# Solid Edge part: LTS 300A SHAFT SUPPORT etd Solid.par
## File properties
Author: davee
Template: Normal.par
Last saved by: davee
Revision: 8
Application: Solid Edge
Accuracy: 0.990
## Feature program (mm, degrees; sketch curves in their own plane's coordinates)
sketch for "unnamed Protrusion 1" #1 plane through (0, 0, 0) normal (0, 0, 1) x-axis (1, 0, 0)
  line (9.5, -14.5) -> (28.5, -14.5)
  line (28.5, -14.5) -> (28.5, 10)
  line (28.5, 10) -> (9.5, 10)
  line (9.5, 10) -> (9.5, -14.5)
sketch for "unnamed Protrusion 1" #2 plane through (0, 0, 0) normal (0, 0, 1) x-axis (1, 0, 0)
  line (-28.5, -10) -> (-9.5, -10)
  line (-9.5, -10) -> (-9.5, 10)
  line (-9.5, 10) -> (-28.5, 10)
  line (-28.5, 10) -> (-28.5, -10)
  dimension (linear) = 9.5
  dimension (linear) = 28.5
  dimension (linear) = 28.5
  dimension (linear) = 28.5
extrude "unnamed Protrusion 1" add finite 13 along +normal
sketch for "ExtrudedProtrusion_2" plane through (-18.5, 0, 13) normal (0, 0, 1) x-axis (1, 0, 0)
  line (-10, 10) -> (47, 10)
  line (47, 2) -> (47, 10)
  line (-10, 2) -> (47, 2)
  line (-10, 10) -> (-10, 2)
extrude "ExtrudedProtrusion_2" add finite 57.5 along +normal
sketch for "unnamed Cutout 1" plane through (0, 2, 41.75) normal (0, -1, 0) x-axis (1, 0, 0)
  circle centre (0, 2.25) radius 10
extrude "unnamed Cutout 1" cut through along -normal
sketch for "ExtrudedCutout_2" plane through (0, 2, 41.75) normal (0, -1, 0) x-axis (1, 0, 0)
  line (2.45, 13.25) -> (6.3509, 13.25)
  line (6.3509, 13.25) -> (12.7017, 2.25)
  line (12.7017, 2.25) -> (6.3509, -8.75)
  line (2.45, -8.75) -> (6.3509, -8.75)
  line (2.45, -7.75) -> (2.45, -8.75)
  line (-2.45, -7.75) -> (2.45, -7.75)
  line (-2.45, -7.75) -> (-2.45, -8.75)
  line (-6.3509, -8.75) -> (-2.45, -8.75)
  line (-12.7017, 2.25) -> (-6.3509, -8.75)
  line (-6.3509, 13.25) -> (-12.7017, 2.25)
  line (-6.3509, 13.25) -> (-2.45, 13.25)
  line (-2.45, 13.25) -> (-2.45, 12.25)
  line (-2.45, 12.25) -> (2.45, 12.25)
  line (2.45, 12.25) -> (2.45, 13.25)
  dimension (linear) = 6.3509
  dimension (linear) = 6.3509
  dimension (linear) = 6.3509
  dimension (linear) = 12.7017
  dimension (linear) = 6.3509
  dimension (linear) = 12.7017
  dimension (linear) = 2.45
  dimension (linear) = 2.45
extrude "ExtrudedCutout_2" cut finite 4 along -normal
sketch for "Hole_1" plane through (-18.5, 0, 0) normal (0, 0, -1) x-axis (1, 0, 0)
  hole centre (35.5, 6.5) bore radius 1.1
hole "Hole_1" diameter 2.2 through
sketch for "unnamed Hole 1" plane through (-18.5, 0, 0) normal (0, 0, -1) x-axis (1, 0, 0)
  hole centre (1.5, 2) bore radius 1.1
hole "unnamed Hole 1" through
sketch for "Hole_3" plane through (-18.5, 0, 0) normal (0, 0, -1) x-axis (1, 0, 0)
  hole centre (1.5, 2) bore radius 2.2
hole "Hole_3" diameter 4.4 finite  VBottomAngle = 118 deg
sketch for "unnamed Hole 2" plane through (-18.5, 0, 0) normal (0, 0, -1) x-axis (1, 0, 0)
  hole centre (35.5, 6.5) bore radius 2.2
hole "unnamed Hole 2" finite
sketch for "Hole_5" plane through (-19, 0, 0) normal (0, 0, -1) x-axis (1, 0, 0)
  hole centre (-2, 2) bore radius 1.65
hole "Hole_5" diameter 3.3 through
sketch for "unnamed Hole 3" plane through (-19, 0, 0) normal (0, 0, -1) x-axis (1, 0, 0)
  hole centre (40, 6.5) bore radius 1.65
hole "unnamed Hole 3" through
sketch for "ExtrudedCutout_3" #1 plane through (-19, -4, 0) normal (0, 0, -1) x-axis (1, 0, 0)
  line (36, 1.5) -> (40, 1.5)
  line (40, 1.5) -> (40, 3.5)
  line (40, 3.5) -> (36, 3.5)
  line (36, 3.5) -> (36, 1.5)
sketch for "ExtrudedCutout_3" #2 plane through (-19, -4, 0) normal (0, 0, -1) x-axis (1, 0, 0)
  line (-2, -3) -> (2, -3)
  line (2, -3) -> (2, -1)
  line (2, -1) -> (-2, -1)
  line (-2, -1) -> (-2, -3)
extrude "ExtrudedCutout_3" cut finite 8 along -normal
sketch for "ExtrudedProtrusion_4" plane through (-19, -4, 13) normal (0, 0, 1) x-axis (1, 0, 0)
  line (5.9213, -0.4) -> (32.0787, -0.4)
  line (32.0787, -0.4) -> (32.0787, 14)
  line (5.9213, 14) -> (32.0787, 14)
  line (5.9213, 14) -> (5.9213, -0.4)
extrude "ExtrudedProtrusion_4" add finite 5.5 along -normal
sketch for "ExtrudedCutout_4" plane through (0, 2, 41.75) normal (0, -1, 0) x-axis (1, 0, 0)
  circle centre (0, -4.25) radius 27
extrude "ExtrudedCutout_4" cut finite 69.85 along +normal
sketch for "ExtrudedCutout_8" plane through (0, 2, 40.5) normal (0, -1, 0) x-axis (1, 0, 0)
  line (25.5, -27.5) -> (28.5, -27.5)
  line (25.5, 3.5) -> (25.5, -27.5)
  line (-25.5, 3.5) -> (-25.5, -27.5)
  line (-28.5, -27.5) -> (-25.5, -27.5)
  line (-28.5, 30) -> (-28.5, -27.5)
  line (-28.5, 30) -> (28.5, 30)
  line (28.5, 30) -> (28.5, -27.4)
extrude "ExtrudedCutout_8" cut finite 4 along -normal
sketch for "ExtrudedProtrusion_5" plane through (0, 6, 41.75) normal (0, -1, 0) x-axis (1, 0, 0)
  line (-25.5, 28.75) -> (-25.5, -28.75)
  line (-25.5, -28.75) -> (-28.5, -28.75)
  line (-28.5, 28.75) -> (-28.5, -28.75)
  line (-28.5, 28.75) -> (-25.5, 28.75)
extrude "ExtrudedProtrusion_5" add finite 20 along +normal
sketch for "ExtrudedCutout_9" plane through (-28.5, -2, 35.25) normal (-1, 0, 0) x-axis (0, -1, 0)
  line (-8, 35.25) -> (6, -15.45)
  line (6, -22.25) -> (6, -15.45)
  line (6, -22.25) -> (18.4691, -22.25)
  dimension (linear) = 6
  dimension (linear) = 6
extrude "ExtrudedCutout_9" cut finite 3 along -normal
sketch for "ExtrudedProtrusion_6" plane through (1.5, 6, 41.75) normal (0, -1, 0) x-axis (1, 0, 0)
  line (24, -28.75) -> (24, 28.75)
  line (24, 28.75) -> (27, 28.75)
  line (27, 28.75) -> (27, -28.75)
  line (27, -28.75) -> (24, -28.75)
extrude "ExtrudedProtrusion_6" add finite 31.75 along +normal
sketch for "ExtrudedCutout_10" plane through (28.5, -7.875, 35.25) normal (1, 0, 0) x-axis (0, 1, 0)
  line (-6.625, -22.25) -> (-4.625, -22.25)
  line (-4.625, -16.07) -> (-4.625, -22.25)
  line (13.875, 35.25) -> (-4.625, -16.07)
  dimension (linear) = 6.625
  dimension (linear) = 4.625
extrude "ExtrudedCutout_10" cut finite 3 along -normal
fillet "Round_1" radius 2
fillet "Round_2" radius 3
fillet "Round_3" radius 0.8
sketch for "unnamed Protrusion 2" plane through (19, -2.25, 0) normal (0, 0, -1) x-axis (-1, 0, 0)
extrude "unnamed Protrusion 2" add to key point along -normal
sketch for "unnamed Protrusion 3" plane through (-19, 0, 0) normal (0, 0, -1) x-axis (-1, 0, 0)
extrude "unnamed Protrusion 3" add to key point along -normal
sketch for "unnamed Protrusion 4" plane through (0, 10, 35.85) normal (0, 1, 0) x-axis (0, 0, -1)
  circle centre (-8.15, 0) radius 14.1374
extrude "unnamed Protrusion 4" add to key point along -normal
pattern "unnamed Pattern 1" of "Hole_1", "unnamed Hole 1"
pattern "unnamed Pattern 2" of "Hole_3", "unnamed Hole 2"
pattern "unnamed Pattern 3" of "Hole_5", "unnamed Hole 3"
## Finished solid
Body 1: solid body, 58 faces, 126 edges, 70 vertices.
  Faces by surface: cylinder 25, plane 21, sphere 6, torus 4, blend 2
  Edges by curve: line 76, circle 40, ellipse 10
Bounding box of the edges (mm; curved faces can reach further): 57.000 x 24.500 x 70.500, from (-28.5, -14.5, 0) to (28.5, 10, 70.5).
Cylindrical faces by radius (mm): R0.8 x3, R2 x19, R3 x2, R25.5 x1
Toroidal faces (ring radius, tube radius in mm): R2.2 r0.8 x2, R4 r2 x2
Spherical faces by radius (mm): R2 x6
Planar faces by outward normal: +x 3, +y 1, +z 2, -x 3, -y 7, -z 3, oblique 2
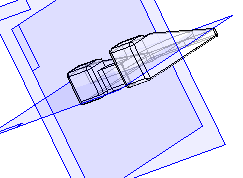
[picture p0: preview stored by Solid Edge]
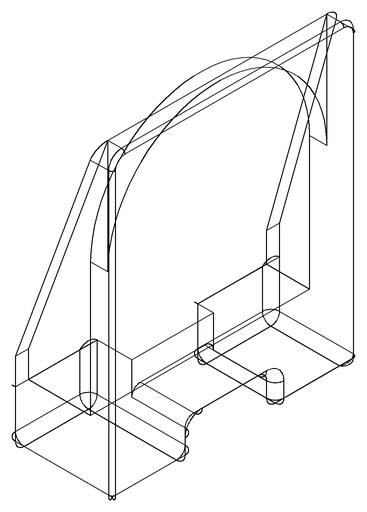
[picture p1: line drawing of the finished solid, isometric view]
